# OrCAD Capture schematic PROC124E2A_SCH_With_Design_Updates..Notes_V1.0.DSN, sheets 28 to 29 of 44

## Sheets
28 27. XDS110 DEBUGGER: size C; title: XDS110 DEBUGGER
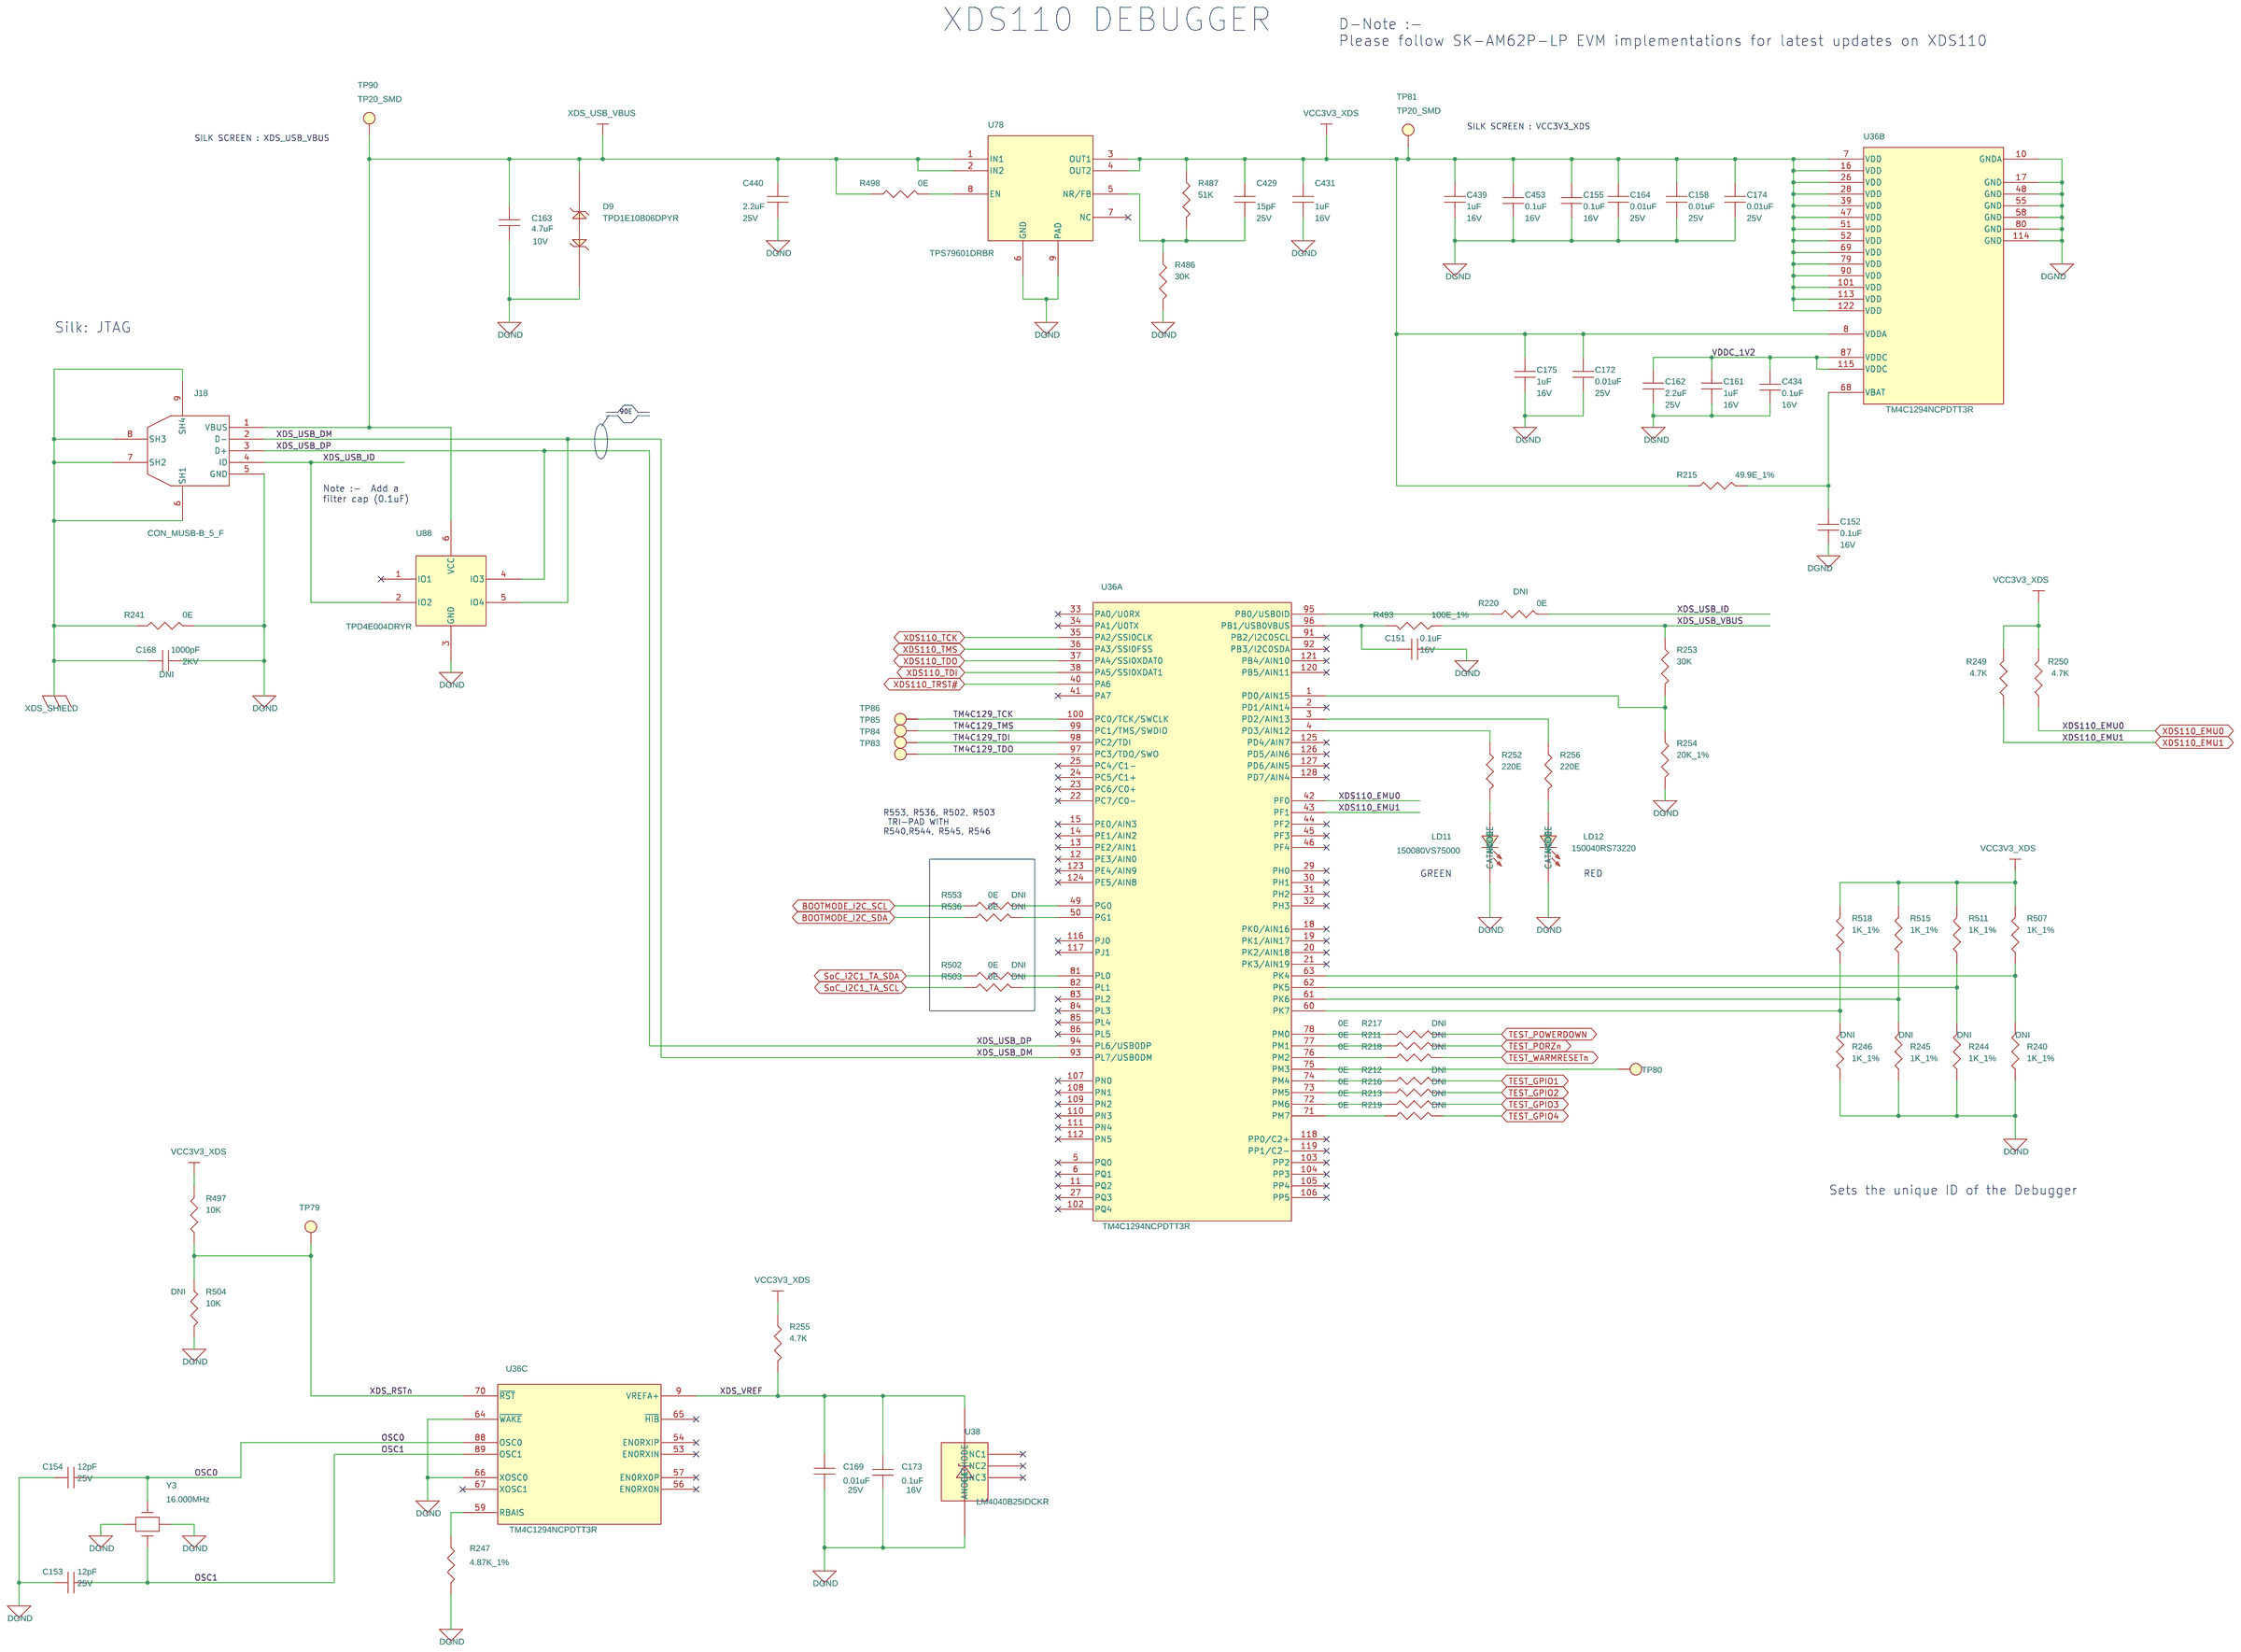
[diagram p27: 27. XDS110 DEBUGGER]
29 28. JTAG BUFFER: size C; title: JTAG BUFFER
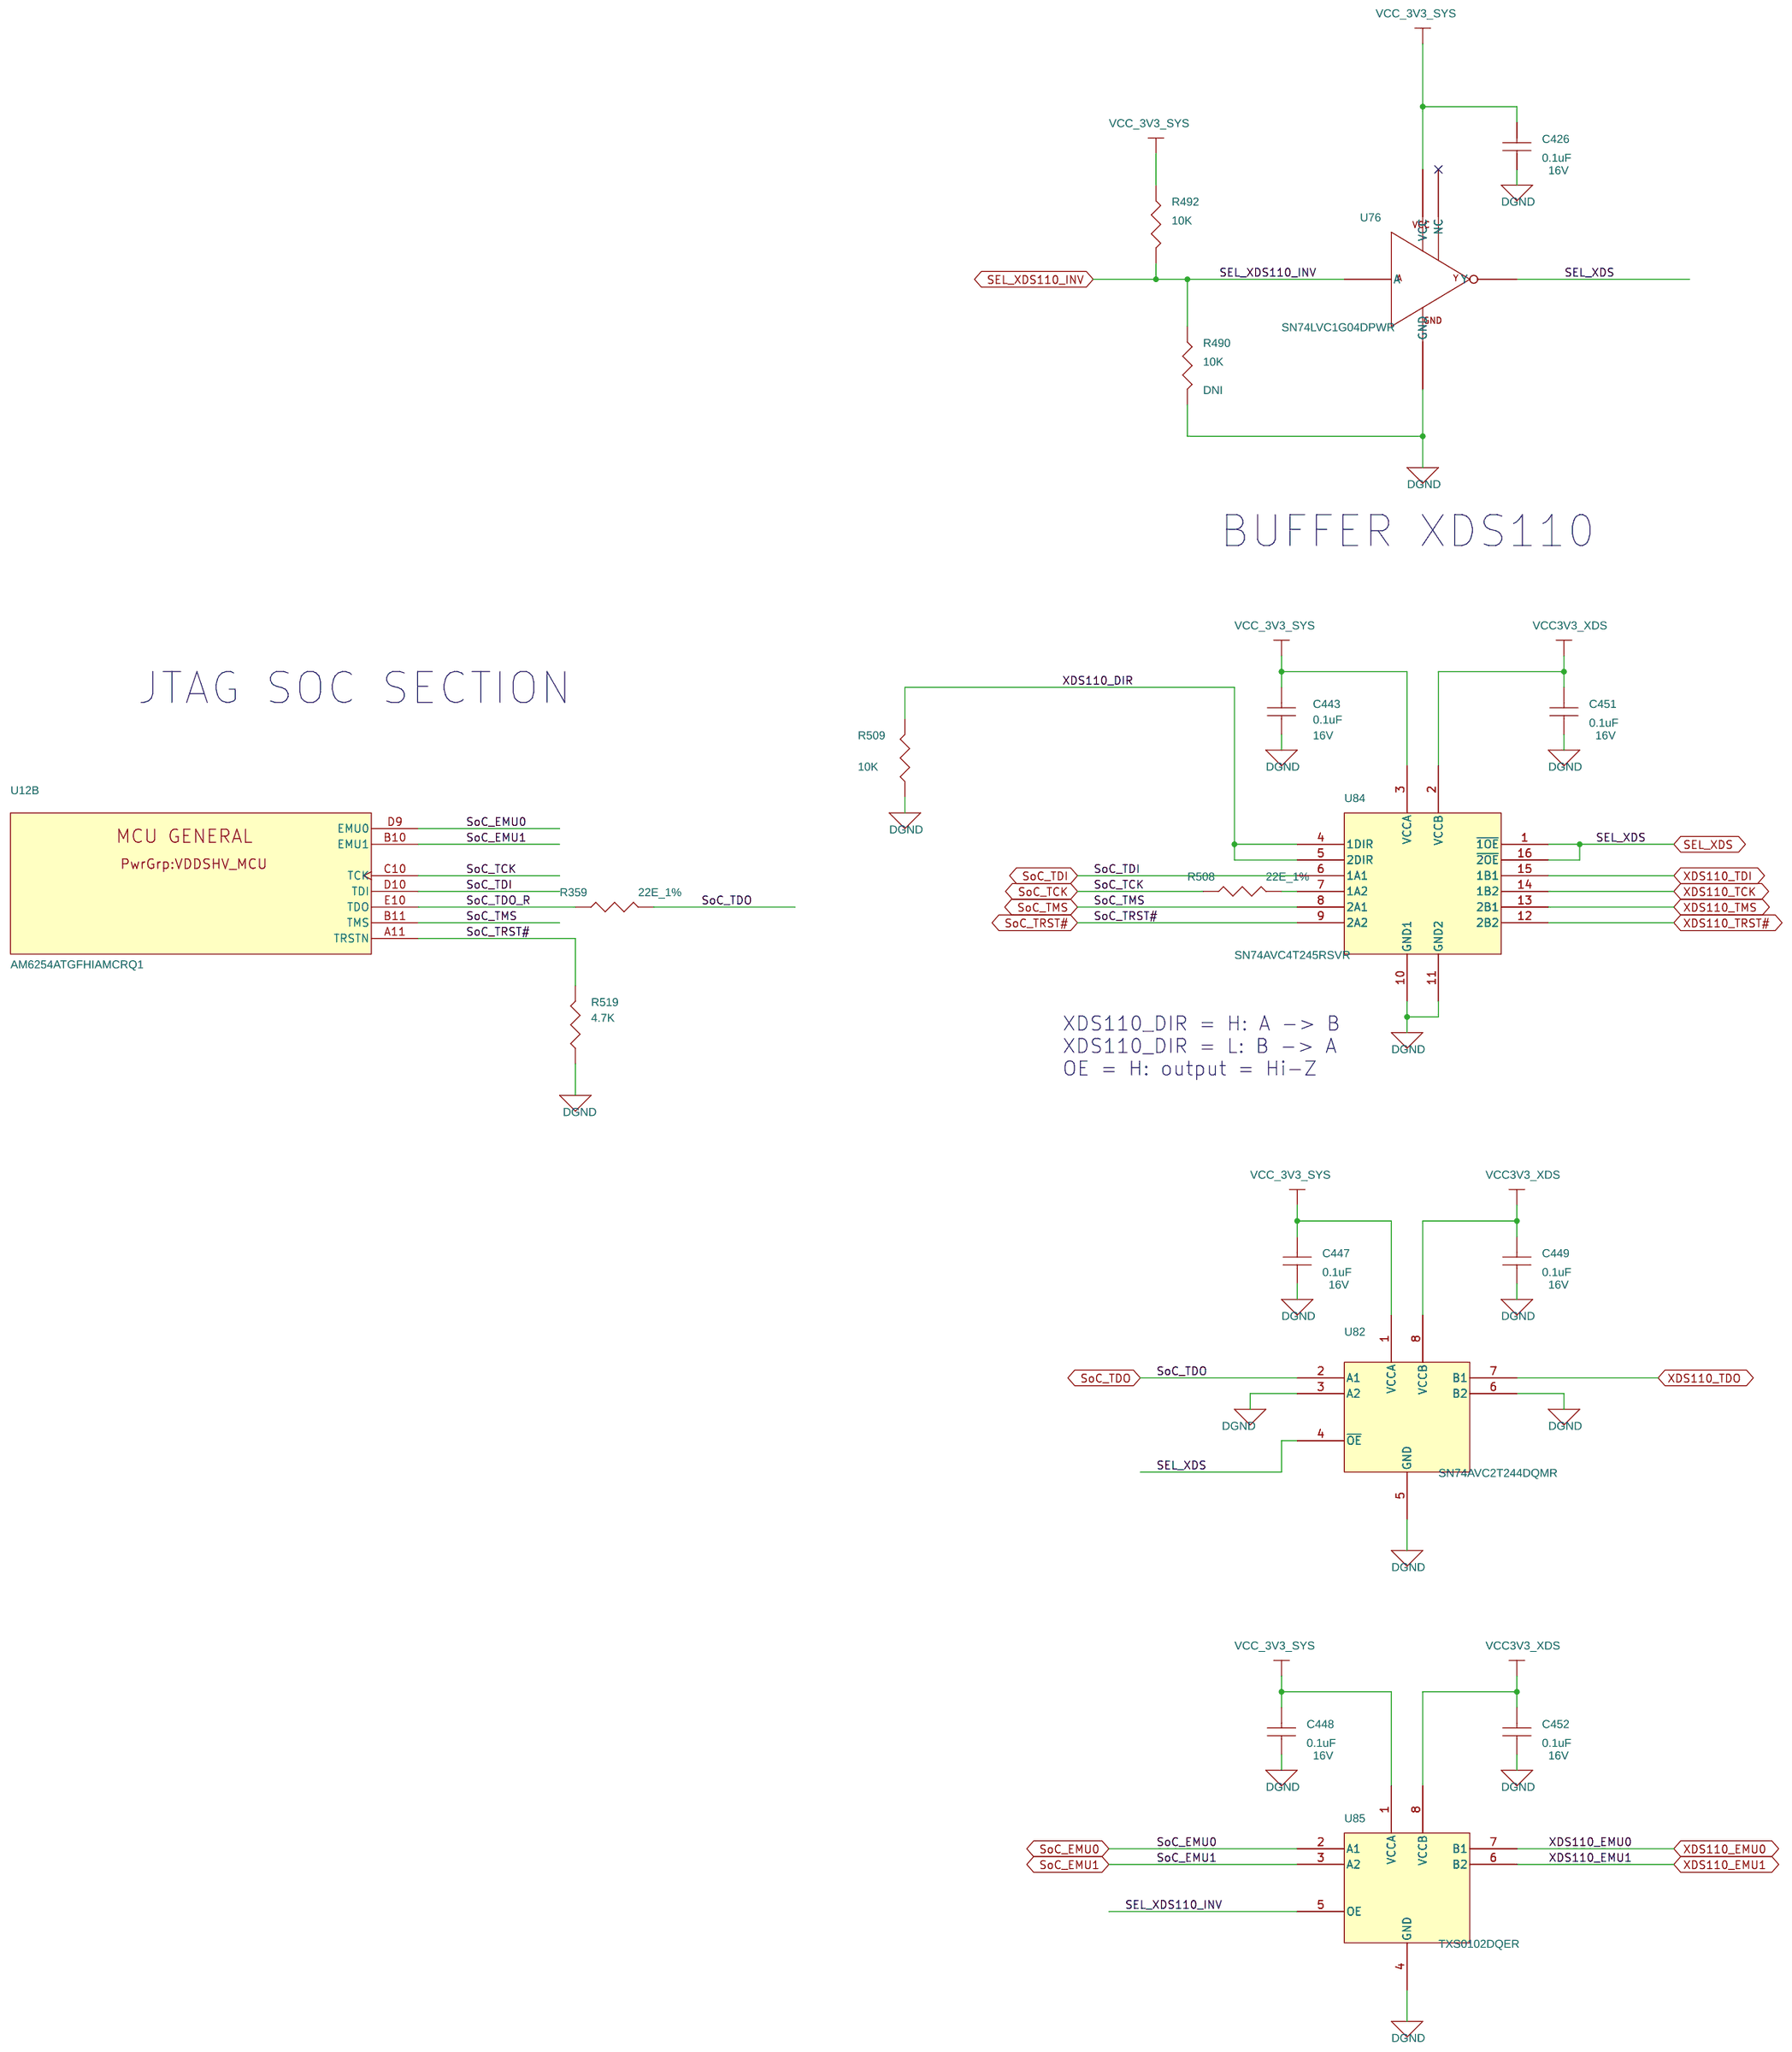
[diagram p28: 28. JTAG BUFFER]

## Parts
sheet 15. SOC POWER CAPS
U12  AM6254ATGFHIAMCRQ1  [FCBGA441_31-49_680X680_2-6]  (sections A,B,C,D,E,F,G,H,I,J,K,L,M,N,O,P,Q,R)
sheet 27. XDS110 DEBUGGER
C151  0.1uF  [CAP0201_0-5]
C152  0.1uF  [CAP0201_0-5]
C153  12pF  [CAP0201_0-5]
C154  12pF  [CAP0201_0-5]
C155  0.1uF  [CAP0201_0-5]
C158  0.01uF  [CAP0201_0-5]
C161  1uF  [CAP0201_0-5]
C162  2.2uF  [CAP0402_0-75]
C163  4.7uF  [CAP0402_0-75]
C164  0.01uF  [CAP0201_0-5]
C168  1000pF  [CAP1206_1-75]
C169  0.01uF  [CAP0201_0-5]
C172  0.01uF  [CAP0201_0-5]
C173  0.1uF  [CAP0201_0-5]
C174  0.01uF  [CAP0201_0-5]
C175  1uF  [CAP0201_0-5]
C429  15pF  [CAP0201_0-5]
C431  1uF  [CAP0201_0-5]
C434  0.1uF  [CAP0201_0-5]
C439  1uF  [CAP0201_0-5]
C440  2.2uF  [CAP0402_0-75]
C453  0.1uF  [CAP0201_0-5]
D9  TPD1E10B06DPYR  [DIO_DFN0402_0-5]
J18  CON_MUSB-B_5_F  [CON_MUSBB5_629105150521_S_R_S_2-7]
LD11  150080VS75000  [LED_150080VS75000_80X50_SMD_0-8]
LD12  150040RS73220  [LED_150040GS73220_40X20_SMD_0-4]
R211  0E  [RES0201_0-5]
R212  0E  [RES0201_0-5]
R213  0E  [RES0201_0-5]
R215  49.9E_1%  [RES0402_0-5]
R216  0E  [RES0201_0-5]
R217  0E  [RES0201_0-5]
R218  0E  [RES0201_0-5]
R219  0E  [RES0201_0-5]
R220  0E  [RES0201_0-5]
R240  1K_1%  [RES0402_0-5]
R241  0E  [RES0603_0-75]
R244  1K_1%  [RES0402_0-5]
R245  1K_1%  [RES0402_0-5]
R246  1K_1%  [RES0402_0-5]
R247  4.87K_1%  [RES0402_0-5]
R249  4.7K  [RES0201_0-5]
R250  4.7K  [RES0201_0-5]
R252  220E  [RES0402_0-5]
R253  30K  [RES0402_0-5]
R254  20K_1%  [RES0402_0-5]
R255  4.7K  [RES0201_0-5]
R256  220E  [RES0402_0-5]
R486  30K  [RES0402_0-5]
R487  51K  [RES0402_0-5]
R493  100E_1%  [RES0402_0-5]
R497  10K  [RES0201_0-5]
R498  0E  [RES0201_0-5]
R502  0E  [RES0201_0-5]
R503  0E  [RES0201_0-5]
R504  10K  [RES0201_0-5]
R507  1K_1%  [RES0402_0-5]
R511  1K_1%  [RES0402_0-5]
R515  1K_1%  [RES0402_0-5]
R518  1K_1%  [RES0402_0-5]
R536  0E  [RES0201_0-5]
R553  0E  [RES0201_0-5]
TP79  TP20_SMD  [TP20_SMD]
TP80  TP20_SMD  [TP20_SMD]
TP81  TP20_SMD  [TP20_SMD]
TP83  TP20_SMD  [TP20_SMD]
TP84  TP20_SMD  [TP20_SMD]
TP85  TP20_SMD  [TP20_SMD]
TP86  TP20_SMD  [TP20_SMD]
TP90  TP20_SMD  [TP20_SMD]
U36  TM4C1294NCPDTT3R  [TQFP128_15-74_550X550_1-2]  (sections A,B,C)
U38  LM4040B25IDCKR  [SC70-5_1-1]
U78  TPS79601DRBR  [SON8_25-59_130X130_1]
U88  TPD4E004DRYR  [SON6_19-68_40X60_PB_0-6]
Y3  16.000MHz  [XTAL4_XRCGB-FM_80X60_SMD_0-7]
sheet 28. JTAG BUFFER
C426  0.1uF  [CAP0201_0-5]
C443  0.1uF  [CAP0201_0-5]
C447  0.1uF  [CAP0201_0-5]
C448  0.1uF  [CAP0201_0-5]
C449  0.1uF  [CAP0201_0-5]
C451  0.1uF  [CAP0201_0-5]
C452  0.1uF  [CAP0201_0-5]
R359  22E_1%  [RES0201_0-5]
R490  10K  [RES0201_0-5]
R492  10K  [RES0201_0-5]
R508  22E_1%  [RES0201_0-5]
R509  10K  [RES0201_0-5]
R519  4.7K  [RES0201_0-5]
U76  SN74LVC1G04DPWR  [X2SON5_TLV7021_30X30_0-4]
U82  SN74AVC2T244DQMR  [X2SON8_15-74_70X50]
U84  SN74AVC4T245RSVR  [UQFN16_TMUX1574_70X100_0-6]
U85  TXS0102DQER  [X2SON8_TXS0102_40X60_0-4]

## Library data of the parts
U12 = AM6254ATGFHIAMCRQ1_FCBGA441: IC AM62Q SoC MICROPROCESSOR FCBGA441; Chkd/date: PRADEEP/180324; Crtd /date: TAMILARASU/180324; Custom_Duty: 15%; Customs_HS_Code: 85423100; Distributor_name: NA; Distributor_part_number: NA; Footprint Path: Y:\MIS_DATABASE\Library\ALTIUM_TOOL\PCB_FOOTPRINTS\Altium_Footprint_Lib.PcbLib; Height: 2.57MM; Library Path: Y:\MIS_DATABASE\Library\ALTIUM_TOOL\SCHEMATICS_PARTS\MS_MICROPROCESSOR_Library.schlib; Mfr_name: TEXAS INSTRUMENTS; Mistral Part No: 141224030001-R; Package: FCBGA441; Part_type: ICS\DIGITAL\MICROPROCESSOR; Project: TI_AM62Q_BRD; RoHS: NA; Temperature: NA; Tolerance: NA; Voltage: NA; Wattage: NA; Weight: NA; Datasheet: Y:\MIS_DATABASE\DATASHEETS\ICS\DIGITAL\MICROCONTROLLER\AM62Q-SoC.PDF
C151 C152 C155 C173 C426 C434 C443 C447-C449 C451-C453 = CAP: CAP CERAMIC 0.1uF 16V 10% X5R 0201; Alt_Mfr_name: YAGEO AMERICA; Alt_Mfr_part_number: CC0402KRX5R8BB104; Chkd/date: MANIRAJA/230118; Crtd /date: MANIRAJA/230118; Custom_Duty: 15%; Customs_HS_Code: 85322990; Distributor_name: DIGIKEY; Distributor_part_number: 490-14305-1-ND; Footprint Path: Y:\MIS_DATABASE\Library\ALTIUM_TOOL\PCB_FOOTPRINTS\Altium_Footprint_Lib.PcbLib; Height: 0.33MM; Library Path: Y:\MIS_DATABASE\Library\ALTIUM_TOOL\SCHEMATICS_PARTS\MS_DISCRETE_Library.schlib; Mfr_name: MURATA; Mfr_part_number: GRM033R61C104KE14D; Mistral Part No: 120009030072-R; Package: 0201; Part_type: CAPACITORS\CERAMIC; Project: TI_MAXIE_CPB; RoHS: RoHS; Temperature: -55°C+85°C; Tolerance: 10%; Voltage: 16V; Wattage: NA; Weight: 0.33mg; Datasheet: Y:\MIS_DATABASE\DATASHEETS\CAPACITORS\GRM033R61C104KE14.PDF
C153 C154 = CAP: CAP CERAMIC 12pF 25V 5% C0G(NP0) 0201; Chkd/date: MANIRAJA/020620; Crtd /date: ALVY/300520; Custom_Duty: 15%; Customs_HS_Code: 85322990; Distributor_name: DIGIKEY; Distributor_part_number: 490-3144-1-ND; Footprint Path: Y:\MIS_DATABASE\Library\ALTIUM_TOOL\PCB_FOOTPRINTS\Altium_Footprint_Lib.PcbLib; Height: 0.33MM; Library Path: Y:\MIS_DATABASE\Library\ALTIUM_TOOL\SCHEMATICS_PARTS\MS_DISCRETE_Library.schlib; Mfr_name: MURATA; Mfr_part_number: GRM0335C1E120JA01D; Mistral Part No: 120009030213-R; Package: 0201; Part_type: CAPACITORS\CERAMIC; Project: QCS610_NANOSOM; RoHS: RoHS; Temperature: -55°C+125°C; Tolerance: 5%; Voltage: 25V; Wattage: NA; Weight: 0.33mg; Datasheet: Y:\MIS_DATABASE\DATASHEETS\CAPACITORS\GRM0335C1E120JA01.PDF
C158 C164 C169 C172 C174 = CAP: CAP CERAMIC 0.01uF 25V 10% X5R 0201; Chkd/date: MANIRAJA/230118; Crtd /date: MANIRAJA/230118; Custom_Duty: 15%; Customs_HS_Code: 85322990; Distributor_name: DIGIKEY; Distributor_part_number: GRM033R61E103KA12J-ND; Footprint Path: Y:\MIS_DATABASE\Library\ALTIUM_TOOL\PCB_FOOTPRINTS\Altium_Footprint_Lib.PcbLib; Height: 0.33MM; Library Path: Y:\MIS_DATABASE\Library\ALTIUM_TOOL\SCHEMATICS_PARTS\MS_DISCRETE_Library.schlib; Mfr_name: MURATA; Mfr_part_number: GRM033R61E103KA12J; Mistral Part No: 120018010007-R; Package: 0201; Part_type: CAPACITORS\CERAMIC; Project: TI_MAXIE_CPB; RoHS: RoHS; Temperature: -55°C+85°C; Tolerance: 10%; Voltage: 25V; Wattage: NA; Weight: 0.33mg; Datasheet: Y:\MIS_DATABASE\DATASHEETS\CAPACITORS\GRM033R61E103KA12.PDF
C161 C175 C431 C439 = CAP: CAP CERAMIC 1uF 16V 20% X5R 0201; Chkd/date: MANIRAJA/300520; Crtd /date: ALVY/260520; Custom_Duty: 15%; Customs_HS_Code: 85322990; Distributor_name: DIGIKEY; Distributor_part_number: 490-18654-1-ND; Footprint Path: Y:\MIS_DATABASE\Library\ALTIUM_TOOL\PCB_FOOTPRINTS\Altium_Footprint_Lib.PcbLib; Height: 0.39MM; Library Path: Y:\MIS_DATABASE\Library\ALTIUM_TOOL\SCHEMATICS_PARTS\MS_DISCRETE_Library.schlib; Mfr_name: MURATA; Mfr_part_number: GRM033R61C105ME15D; Mistral Part No: 120018090038-R; Package: 0201; Part_type: CAPACITORS\CERAMIC; Project: QCS610_NANOSOM; RoHS: RoHS; Temperature: -55°C+85°C; Tolerance: 20%; Voltage: 16V; Wattage: NA; Weight: 0.33mg; Datasheet: Y:\MIS_DATABASE\DATASHEETS\CAPACITORS\GRM033R61C105ME15.PDF
C162 C440 = CAP: CAP CERAMIC 2.2uF 25V 10% X5R 0402; Chkd/date: ALVY/010721; Crtd /date: MANIRAJA/010721; Custom_Duty: 15%; Customs_HS_Code: 85322990; Distributor_name: DIGIKEY; Distributor_part_number: 490-12703-1-ND; Footprint Path: Y:\MIS_DATABASE\Library\ALTIUM_TOOL\PCB_FOOTPRINTS\Altium_Footprint_Lib.PcbLib; Height: 0.70MM; Library Path: Y:\MIS_DATABASE\Library\ALTIUM_TOOL\SCHEMATICS_PARTS\MS_DISCRETE_Library.schlib; Mfr_name: MURATA; Mfr_part_number: GRM155R61E225KE11D; Mistral Part No: 120015120001-R; Package: 0402; Part_type: CAPACITORS\CERAMIC; Project: TI_AM263X_CC; RoHS: RoHS; Temperature: -55°C+85°C; Tolerance: 10%; Voltage: 25V; Wattage: NA; Weight: 1.5mg; Datasheet: Y:\MIS_DATABASE\DATASHEETS\CAPACITORS\GRM155R61E225KE11.PDF
C163 = CAP: CAP CERAMIC 4.7uF 10V 20% X5R 0402; Chkd/date: MANIRAJA/110718; Crtd /date: ALVY/110718; Custom_Duty: 15%; Customs_HS_Code: 85322990; Distributor_name: DIGIKEY; Distributor_part_number: 490-14306-1-ND; Footprint Path: Y:\MIS_DATABASE\Library\ALTIUM_TOOL\PCB_FOOTPRINTS\Altium_Footprint_Lib.PcbLib; Height: 0.65MM; Library Path: Y:\MIS_DATABASE\Library\ALTIUM_TOOL\SCHEMATICS_PARTS\MS_DISCRETE_Library.schlib; Mfr_name: MURATA; Mfr_part_number: GRM155R61A475MEAAD; Mistral Part No: 120012060002-R; Package: 0402; Part_type: CAPACITORS\CERAMIC; Project: TI_J7SVB_PCIE_ADD-ON-CARD; RoHS: RoHS; Temperature: -55°C+85°C; Tolerance: 20%; Voltage: 10V; Wattage: NA; Weight: 14mg; Datasheet: Y:\MIS_DATABASE\DATASHEETS\CAPACITORS\GRM155R61A475MEAAD.PDF
C168 = CAP: CAP CERAMIC 1000pF 2KV 10% X7R 1206; Assembly_Instruction: DNI; Chkd/date: SHREESHAIL/291106; Crtd /date: MAZHAR/281106; Custom_Duty: 15%; Customs_HS_Code: 85322990; Distributor_name: DIGIKEY; Distributor_part_number: 478-2956-1-ND; Footprint Path: Y:\MIS_DATABASE\Library\ALTIUM_TOOL\PCB_FOOTPRINTS\Altium_Footprint_Lib.PcbLib; Height: 1.52MM; Library Path: Y:\MIS_DATABASE\Library\ALTIUM_TOOL\SCHEMATICS_PARTS\MS_DISCRETE_Library.schlib; Mfr_name: AVX CORPORATION; Mfr_part_number: 1206GC102KAT1A; Mistral Part No: 120015080006-R; Package: 1206; Part_type: CAPACITORS\CERAMIC; Project: ADR1B; RoHS: RoHS; Temperature: -55°C+125°C; Tolerance: 10%; Voltage: 2KV; Wattage: NA; Weight: 16.2mg; Datasheet: Y:\MIS_DATABASE\DATASHEETS\CAPACITORS\AVX_HV-MLC.PDF
C429 = CAP: CAP CERAMIC 15pF 25V 2% HI-Q C0G(NP0) 0201; Chkd/date: VASANTHA/081216; Crtd /date: MANIRAJA/081216; Custom_Duty: 15%; Customs_HS_Code: 85322990; Distributor_name: DIGIKEY; Distributor_part_number: 490-10562-1-ND; Footprint Path: Y:\MIS_DATABASE\Library\ALTIUM_TOOL\PCB_FOOTPRINTS\Altium_Footprint_Lib.PcbLib; Height: 0.33MM; Library Path: Y:\MIS_DATABASE\Library\ALTIUM_TOOL\SCHEMATICS_PARTS\MS_DISCRETE_Library.schlib; Mfr_name: MURATA; Mfr_part_number: GJM0335C1E150GB01D; Mistral Part No: 120016120011-R; Package: 0201; Part_type: CAPACITORS\CERAMIC; Project: OCTBTS5200; RoHS: RoHS; Temperature: -55°C+125°C; Tolerance: 2%; Voltage: 25V; Wattage: NA; Weight: 0.33mg; Datasheet: Y:\MIS_DATABASE\DATASHEETS\CAPACITORS\MURATA-GXX-SER_NOV17.PDF
D9 = DIODE_SOD323: DIODE 1CH ESD PROTECTION X1SON2; Chkd/date: MANIRAJA/040420; Crtd /date: VASANTHA/181114; Custom_Duty: 15%; Customs_HS_Code: 85423100; Distributor_name: DIGIKEY; Distributor_part_number: 296-30406-1-ND; Footprint Path: Y:\MIS_DATABASE\Library\ALTIUM_TOOL\PCB_FOOTPRINTS\Altium_Footprint_Lib.PcbLib; Height: 0.45MM; Library Path: Y:\MIS_DATABASE\Library\ALTIUM_TOOL\SCHEMATICS_PARTS\MS_DISCRETE_Library.schlib; Mfr_name: TEXAS INSTRUMENTS; Mistral Part No: 130014110022-R; Package: X1SON2; Part_type: DIODE; Project: GALILEO_EVM; RoHS: RoHS; Temperature: -40°C+125°C; Tolerance: NA; Voltage: NA; Wattage: NA; Weight: 1mg; Datasheet: Y:\MIS_DATABASE\DATASHEETS\ICS\INTERFACE\TPD1E10B06-SER.PDF
J18 = CON_USB_MINI-B: CON MICRO USB TYPE B 5POS FEMALE RT SMD; Chkd/date: MANIRAJA/150519; Crtd /date: ALVY/150519; Custom_Duty: 24%; Customs_HS_Code: 85369090; Distributor_name: DIGIKEY; Distributor_part_number: 732-5960-1-ND; Footprint Path: Y:\MIS_DATABASE\Library\ALTIUM_TOOL\PCB_FOOTPRINTS\Altium_Footprint_Lib.PcbLib; Height: 2.66MM; Library Path: Y:\MIS_DATABASE\Library\ALTIUM_TOOL\SCHEMATICS_PARTS\MS_CONNECTOR_Library.schlib; Mfr_name: WURTH ELECTRONICS; Mfr_part_number: 629105150521; Mistral Part No: 150019050015-R; Package: SMD; Part_type: CONNECTOR\USB; Project: NEXTNAV_ALT-STATION_ATE_BRD; RoHS: RoHS; Temperature: -40°C+85°C; Tolerance: NA; Voltage: NA; Wattage: NA; Weight: 360mg; Datasheet: Y:\MIS_DATABASE\DATASHEETS\CONNECTORS\629105150521.PDF
LD11 = DIODE_LED: DIODE LED BRIGHT GREEN SMD; Chkd/date: MANIRAJA/180820; Crtd /date: ALVY/180820; Custom_Duty: 24%; Customs_HS_Code: 85439000; Distributor_name: DIGIKEY; Distributor_part_number: 732-4986-1-ND; Footprint Path: Y:\MIS_DATABASE\Library\ALTIUM_TOOL\PCB_FOOTPRINTS\Altium_Footprint_Lib.PcbLib; Height: 0.80MM; Library Path: Y:\MIS_DATABASE\Library\ALTIUM_TOOL\SCHEMATICS_PARTS\MS_OPTO_Library.schlib; Mfr_name: WURTH ELECTRONICS; Mistral Part No: 130020080012-R; Package: SMD; Part_type: OPTO\LED; Project: AM64x_EVM_BRD; RoHS: RoHS; Temperature: -40°C+85°C; Tolerance: NA; Voltage: NA; Wattage: NA; Weight: 10mg; Datasheet: Y:\MIS_DATABASE\DATASHEETS\DISCRETES\LEDS\150080VS75000.PDF
LD12 = DIODE_LED: DIODE LED RED SMD; Chkd/date: MANIRAJA/100920; Crtd /date: ALVY/100920; Custom_Duty: 24%; Customs_HS_Code: 85439000; Distributor_name: DIGIKEY; Distributor_part_number: 732-13422-1-ND; Footprint Path: Y:\MIS_DATABASE\Library\ALTIUM_TOOL\PCB_FOOTPRINTS\Altium_Footprint_Lib.PcbLib; Height: 0.35MM; Library Path: Y:\MIS_DATABASE\Library\ALTIUM_TOOL\SCHEMATICS_PARTS\MS_OPTO_Library.schlib; Mfr_name: WURTH ELECTRONICS; Mistral Part No: 130020090020-R; Package: SMD; Part_type: OPTO\LED; Project: AM64X_SKEVM; RoHS: RoHS; Temperature: -40°C+85°C; Tolerance: NA; Voltage: NA; Wattage: NA; Weight: 29.3mg; Datasheet: Y:\MIS_DATABASE\DATASHEETS\DISCRETES\LEDS\150040RS73220.PDF
R211-R213 R216-R220 R502 R503 R536 R553 = RESISTOR: RES 0E 1/20W 5% 0201; Assembly_Instruction: DNI; Chkd/date: NAVEED/301214; Crtd /date: MUDDU/120710; Custom_Duty: 15%; Customs_HS_Code: 85332119; Distributor_name: DIGIKEY; Distributor_part_number: 311-0.0NCT-ND; Footprint Path: Y:\MIS_DATABASE\Library\ALTIUM_TOOL\PCB_FOOTPRINTS\Altium_Footprint_Lib.PcbLib; Height: 0.26MM; Library Path: Y:\MIS_DATABASE\Library\ALTIUM_TOOL\SCHEMATICS_PARTS\MS_DISCRETE_Library.schlib; Mfr_name: YAGEO AMERICA; Mfr_part_number: RC0201JR-070RL; Mistral Part No: 110010070067-R; Package: 0201; Part_type: RESISTORS\FIXED; Project: PB_BUGBASE; RoHS: RoHS; Temperature: -55°C+125°C; Tolerance: 5%; Voltage: NA; Wattage: 1/20W; Weight: 0.17mg; Datasheet: Y:\MIS_DATABASE\DATASHEETS\RESISTORS\RCXXXXL-SER_MAR18.PDF
R215 = RESISTOR: RES 49.9E 1/16W 1% 0402; Chkd/date: MANIRAJA/210519; Crtd /date: MANIRAJA/210519; Custom_Duty: 15%; Customs_HS_Code: 85332119; Distributor_name: DIGIKEY; Distributor_part_number: 541-3967-1-ND; Footprint Path: Y:\MIS_DATABASE\Library\ALTIUM_TOOL\PCB_FOOTPRINTS\Altium_Footprint_Lib.PcbLib; Height: 0.35MM; Library Path: Y:\MIS_DATABASE\Library\ALTIUM_TOOL\SCHEMATICS_PARTS\MS_DISCRETE_Library.schlib; Mfr_name: VISHAY; Mfr_part_number: CRCW040249R9FKEDC; Mistral Part No: 110009030846-R; Package: 0402; Part_type: RESISTORS\FIXED; Project: RFSU_RFTJ_CARD; RoHS: RoHS; Temperature: -55°C+155°C; Tolerance: 1%; Voltage: NA; Wattage: 1/16W; Weight: 0.65mg; Datasheet: Y:\MIS_DATABASE\DATASHEETS\RESISTORS\CRCW_C-SER.PDF
R240 R244-R246 = RESISTOR: RES 1K 1/10W 1% 0402; Assembly_Instruction: DNI; Chkd/date: VASANTHA/281216; Crtd /date: MAZHAR/150506; Custom_Duty: 15%; Customs_HS_Code: 85332119; Distributor_name: DIGIKEY; Distributor_part_number: P1.00KLCT-ND; Footprint Path: Y:\MIS_DATABASE\Library\ALTIUM_TOOL\PCB_FOOTPRINTS\Altium_Footprint_Lib.PcbLib; Height: 0.40MM; Library Path: Y:\MIS_DATABASE\Library\ALTIUM_TOOL\SCHEMATICS_PARTS\MS_DISCRETE_Library.schlib; Mfr_name: PANASONIC-ECG; Mfr_part_number: ERJ-2RKF1001X; Mistral Part No: 110009030411-R; Package: 0402; Part_type: RESISTORS\FIXED; Project: VOCERA; RoHS: RoHS; Temperature: -55°C+155°C; Tolerance: 1%; Voltage: NA; Wattage: 1/10W; Weight: 0.8mg; Datasheet: Y:\MIS_DATABASE\DATASHEETS\RESISTORS\PAN-ERJSER_NOV17.PDF
R241 = RESISTOR: RES 0E 1/10W 5% 0603; Chkd/date: MANIRAJA/051217; Crtd /date: BAVISH/180211; Custom_Duty: 15%; Customs_HS_Code: 85332119; Distributor_name: DIGIKEY; Distributor_part_number: 311-0.0GRCT-ND; Footprint Path: Y:\MIS_DATABASE\Library\ALTIUM_TOOL\PCB_FOOTPRINTS\Altium_Footprint_Lib.PcbLib; Height: 0.55MM; Library Path: Y:\MIS_DATABASE\Library\ALTIUM_TOOL\SCHEMATICS_PARTS\MS_DISCRETE_Library.schlib; Mfr_name: YAGEO AMERICA; Mfr_part_number: RC0603JR-070RL; Mistral Part No: 110011020013-R; Package: 0603; Part_type: RESISTORS\FIXED; Project: KENNEL; RoHS: RoHS; Temperature: -55°C+155°C; Tolerance: 5%; Voltage: NA; Wattage: 1/10W; Weight: 2mg; Datasheet: Y:\MIS_DATABASE\DATASHEETS\RESISTORS\RCXXXXL-SER_MAR18.PDF
R247 = RESISTOR: RES 4.87K 1/10W 1% 0402; Chkd/date: MAZHAR/150709; Crtd /date: USMAN/150109; Custom_Duty: 15%; Customs_HS_Code: 85332119; Distributor_name: DIGIKEY; Distributor_part_number: P4.87KLCT-ND; Footprint Path: Y:\MIS_DATABASE\Library\ALTIUM_TOOL\PCB_FOOTPRINTS\Altium_Footprint_Lib.PcbLib; Height: 0.40MM; Library Path: Y:\MIS_DATABASE\Library\ALTIUM_TOOL\SCHEMATICS_PARTS\MS_DISCRETE_Library.schlib; Mfr_name: PANASONIC-ECG; Mfr_part_number: ERJ-2RKF4871X; Mistral Part No: 110009030803-R; Package: 0402; Part_type: RESISTORS\FIXED; Project: BSN-II; RoHS: RoHS; Temperature: -55°C+155°C; Tolerance: 1%; Voltage: NA; Wattage: 1/10W; Weight: 0.8mg; Datasheet: Y:\MIS_DATABASE\DATASHEETS\RESISTORS\PAN-ERJSER_NOV17.PDF
R249 R250 R255 R519 = RESISTOR: RES 4.7K 1/20W 5% 0201; Chkd/date: MANIRAJA/200921; Crtd /date: ALVY/200921; Custom_Duty: 15%; Customs_HS_Code: 85332119; Distributor_name: DIGIKEY; Distributor_part_number: 311-4.7KNCT-ND; Footprint Path: Y:\MIS_DATABASE\Library\ALTIUM_TOOL\PCB_FOOTPRINTS\Altium_Footprint_Lib.PcbLib; Height: 0.26MM; Library Path: Y:\MIS_DATABASE\Library\ALTIUM_TOOL\SCHEMATICS_PARTS\MS_DISCRETE_Library.schlib; Mfr_name: YAGEO AMERICA; Mfr_part_number: RC0201JR-074K7L; Mistral Part No: 110021090007-R; Package: 0201; Part_type: RESISTORS\FIXED; Project: TI_AM62x SKEVM_BRD; RoHS: RoHS; Temperature: -55°C+125°C; Tolerance: 5%; Voltage: NA; Wattage: 1/20W; Weight: 0.17mg; Datasheet: Y:\MIS_DATABASE\DATASHEETS\RESISTORS\RCXXXXL-SER_MAR18.PDF
R252 R256 = RESISTOR: RES 220E 1/10W 5% 0402; Chkd/date: VASANTHA/291216; Crtd /date: GEETHA/260406; Custom_Duty: 15%; Customs_HS_Code: 85332119; Distributor_name: DIGIKEY; Distributor_part_number: P220JCT-ND; Footprint Path: Y:\MIS_DATABASE\Library\ALTIUM_TOOL\PCB_FOOTPRINTS\Altium_Footprint_Lib.PcbLib; Height: 0.40MM; Library Path: Y:\MIS_DATABASE\Library\ALTIUM_TOOL\SCHEMATICS_PARTS\MS_DISCRETE_Library.schlib; Mfr_name: PANASONIC-ECG; Mfr_part_number: ERJ-2GEJ221X; Mistral Part No: 110009030506-R; Package: 0402; Part_type: RESISTORS\FIXED; Project: RED EYE; RoHS: RoHS; Temperature: -55°C+155°C; Tolerance: 5%; Voltage: NA; Wattage: 1/10W; Weight: 0.8mg; Datasheet: Y:\MIS_DATABASE\DATASHEETS\RESISTORS\PAN-ERJSER_NOV17.PDF
R253 R486 = RESISTOR: RES 30K 1/16W 5% 0402; Chkd/date: MANIRAJA/230817; Crtd /date: MANIRAJA/230817; Custom_Duty: 15%; Customs_HS_Code: 85332119; Distributor_name: DIGIKEY; Distributor_part_number: 541-30KJCT-ND; Footprint Path: Y:\MIS_DATABASE\Library\ALTIUM_TOOL\PCB_FOOTPRINTS\Altium_Footprint_Lib.PcbLib; Height: 0.40MM; Library Path: Y:\MIS_DATABASE\Library\ALTIUM_TOOL\SCHEMATICS_PARTS\MS_DISCRETE_Library.schlib; Mfr_name: VISHAY; Mfr_part_number: CRCW040230K0JNED; Mistral Part No: 110017080023-R; Package: 0402; Part_type: RESISTORS\FIXED; Project: TI_MAXIE_CPB; RoHS: RoHS; Temperature: -55°C+155°C; Tolerance: 5%; Voltage: NA; Wattage: 1/16W; Weight: 0.65mg; Datasheet: Y:\MIS_DATABASE\DATASHEETS\RESISTORS\CRCW0603.PDF
R254 = RESISTOR: RES 20K 1/16W 1% 0402; Chkd/date: MANIRAJA/021120; Crtd /date: MANIRAJA/021120; Custom_Duty: 15%; Customs_HS_Code: 85332119; Distributor_name: DIGIKEY; Distributor_part_number: 541-20.0KLCT-ND; Footprint Path: Y:\MIS_DATABASE\Library\ALTIUM_TOOL\PCB_FOOTPRINTS\Altium_Footprint_Lib.PcbLib; Height: 0.40MM; Library Path: Y:\MIS_DATABASE\Library\ALTIUM_TOOL\SCHEMATICS_PARTS\MS_DISCRETE_Library.schlib; Mfr_name: VISHAY; Mfr_part_number: CRCW040220K0FKED; Mistral Part No: 110009030486-R; Package: 0402; Part_type: RESISTORS\FIXED; Project: VAGG_SBC_BRD; RoHS: RoHS; Temperature: -55°C+155°C; Tolerance: 1%; Voltage: NA; Wattage: 1/16W; Weight: 0.65mg; Datasheet: Y:\MIS_DATABASE\DATASHEETS\RESISTORS\CRCW0603.PDF
R487 = RESISTOR: RES 51K 1/16W 5% 0402; Chkd/date: MANIRAJA/230817; Crtd /date: MANIRAJA/230817; Custom_Duty: 15%; Customs_HS_Code: 85332119; Distributor_name: DIGIKEY; Distributor_part_number: 541-51KJCT-ND; Footprint Path: Y:\MIS_DATABASE\Library\ALTIUM_TOOL\PCB_FOOTPRINTS\Altium_Footprint_Lib.PcbLib; Height: 0.40MM; Library Path: Y:\MIS_DATABASE\Library\ALTIUM_TOOL\SCHEMATICS_PARTS\MS_DISCRETE_Library.schlib; Mfr_name: VISHAY; Mfr_part_number: CRCW040251K0JNED; Mistral Part No: 110009030966-R; Package: 0402; Part_type: RESISTORS\FIXED; Project: TI_MAXIE_CPB; RoHS: RoHS; Temperature: -55°C+155°C; Tolerance: 5%; Voltage: NA; Wattage: 1/16W; Weight: 0.65mg; Datasheet: Y:\MIS_DATABASE\DATASHEETS\RESISTORS\CRCW0603.PDF
R493 = RESISTOR: RES 100E 1/16W 1% 0402; Chkd/date: MANIRAJA/060318; Crtd /date: NAVEED/220714; Custom_Duty: 15%; Customs_HS_Code: 85332119; Distributor_name: DIGIKEY; Distributor_part_number: 311-100LRCT-ND; Footprint Path: Y:\MIS_DATABASE\Library\ALTIUM_TOOL\PCB_FOOTPRINTS\Altium_Footprint_Lib.PcbLib; Height: 0.40MM; Library Path: Y:\MIS_DATABASE\Library\ALTIUM_TOOL\SCHEMATICS_PARTS\MS_DISCRETE_Library.schlib; Mfr_name: YAGEO AMERICA; Mfr_part_number: RC0402FR-07100RL; Mistral Part No: 110014070015-R; Package: 0402; Part_type: RESISTORS\FIXED; Project: DLRU; RoHS: RoHS; Temperature: -55°C+155°C; Tolerance: 1%; Voltage: NA; Wattage: 1/16W; Weight: 0.65mg; Datasheet: Y:\MIS_DATABASE\DATASHEETS\RESISTORS\RCXXXXL-SER_MAR18.PDF
R492 R497 R509 = RESISTOR: RES 10K 1/20W 5% 0201; Chkd/date: MANIRAJA/050517; Crtd /date: MANIRAJA/050517; Custom_Duty: 15%; Customs_HS_Code: 85332119; Distributor_name: DIGIKEY; Distributor_part_number: 311-10KNCT-ND; Footprint Path: Y:\MIS_DATABASE\Library\ALTIUM_TOOL\PCB_FOOTPRINTS\Altium_Footprint_Lib.PcbLib; Height: 0.26MM; Library Path: Y:\MIS_DATABASE\Library\ALTIUM_TOOL\SCHEMATICS_PARTS\MS_DISCRETE_Library.schlib; Mfr_name: YAGEO AMERICA; Mfr_part_number: RC0201JR-0710KL; Mistral Part No: 110010070051-R; Package: 0201; Part_type: RESISTORS\FIXED; Project: GOLDEN-I LITE; RoHS: RoHS; Temperature: -55°C+125°C; Tolerance: 5%; Voltage: NA; Wattage: 1/20W; Weight: 0.17mg; Datasheet: Y:\MIS_DATABASE\DATASHEETS\RESISTORS\RCXXXXL-SER_MAR18.PDF
R498 = RESISTOR: RES 0E 1/20W 5% 0201; Chkd/date: NAVEED/301214; Crtd /date: MUDDU/120710; Custom_Duty: 15%; Customs_HS_Code: 85332119; Distributor_name: DIGIKEY; Distributor_part_number: 311-0.0NCT-ND; Footprint Path: Y:\MIS_DATABASE\Library\ALTIUM_TOOL\PCB_FOOTPRINTS\Altium_Footprint_Lib.PcbLib; Height: 0.26MM; Library Path: Y:\MIS_DATABASE\Library\ALTIUM_TOOL\SCHEMATICS_PARTS\MS_DISCRETE_Library.schlib; Mfr_name: YAGEO AMERICA; Mfr_part_number: RC0201JR-070RL; Mistral Part No: 110010070067-R; Package: 0201; Part_type: RESISTORS\FIXED; Project: PB_BUGBASE; RoHS: RoHS; Temperature: -55°C+125°C; Tolerance: 5%; Voltage: NA; Wattage: 1/20W; Weight: 0.17mg; Datasheet: Y:\MIS_DATABASE\DATASHEETS\RESISTORS\RCXXXXL-SER_MAR18.PDF
R490 R504 = RESISTOR: RES 10K 1/20W 5% 0201; Assembly_Instruction: DNI; Chkd/date: MANIRAJA/050517; Crtd /date: MANIRAJA/050517; Custom_Duty: 15%; Customs_HS_Code: 85332119; Distributor_name: DIGIKEY; Distributor_part_number: 311-10KNCT-ND; Footprint Path: Y:\MIS_DATABASE\Library\ALTIUM_TOOL\PCB_FOOTPRINTS\Altium_Footprint_Lib.PcbLib; Height: 0.26MM; Library Path: Y:\MIS_DATABASE\Library\ALTIUM_TOOL\SCHEMATICS_PARTS\MS_DISCRETE_Library.schlib; Mfr_name: YAGEO AMERICA; Mfr_part_number: RC0201JR-0710KL; Mistral Part No: 110010070051-R; Package: 0201; Part_type: RESISTORS\FIXED; Project: GOLDEN-I LITE; RoHS: RoHS; Temperature: -55°C+125°C; Tolerance: 5%; Voltage: NA; Wattage: 1/20W; Weight: 0.17mg; Datasheet: Y:\MIS_DATABASE\DATASHEETS\RESISTORS\RCXXXXL-SER_MAR18.PDF
R507 R511 R515 R518 = RESISTOR: RES 1K 1/10W 1% 0402; Chkd/date: VASANTHA/281216; Crtd /date: MAZHAR/150506; Custom_Duty: 15%; Customs_HS_Code: 85332119; Distributor_name: DIGIKEY; Distributor_part_number: P1.00KLCT-ND; Footprint Path: Y:\MIS_DATABASE\Library\ALTIUM_TOOL\PCB_FOOTPRINTS\Altium_Footprint_Lib.PcbLib; Height: 0.40MM; Library Path: Y:\MIS_DATABASE\Library\ALTIUM_TOOL\SCHEMATICS_PARTS\MS_DISCRETE_Library.schlib; Mfr_name: PANASONIC-ECG; Mfr_part_number: ERJ-2RKF1001X; Mistral Part No: 110009030411-R; Package: 0402; Part_type: RESISTORS\FIXED; Project: VOCERA; RoHS: RoHS; Temperature: -55°C+155°C; Tolerance: 1%; Voltage: NA; Wattage: 1/10W; Weight: 0.8mg; Datasheet: Y:\MIS_DATABASE\DATASHEETS\RESISTORS\PAN-ERJSER_NOV17.PDF
TP79 TP80 TP83-TP86 = TESTPOINT: TESTPOINT CIR 20 SMD; Chkd/date: SHREESHAIL/171006; Crtd /date: MAZHAR/171006; Custom_Duty: NA; Customs_HS_Code: NA; Distributor_name: NA; Distributor_part_number: NA; Footprint Path: Y:\MIS_DATABASE\Library\ALTIUM_TOOL\PCB_FOOTPRINTS\Altium_Footprint_Lib.PcbLib; Height: NA; Library Path: Y:\MIS_DATABASE\Library\ALTIUM_TOOL\SCHEMATICS_PARTS\MS_DISCRETE_Library.schlib; MECHANICAL 3D STEP FILE: NA; Mfr_name: LOCAL; Mistral Part No: NA; Package: SMD; Project: BT MODULE_CSRBC04; RoHS: NA; Temperature: NA; Tolerance: NA; Voltage: NA; Wattage: NA; Weight: NA; Datasheet: NA
TP81 TP90 = TESTPOINT: TESTPOINT CIR 20 SMD; Chkd/date: SHREESHAIL/171006; Crtd /date: MAZHAR/171006; Custom_Duty: NA; Customs_HS_Code: NA; Distributor_name: NA; Distributor_part_number: NA; Footprint Path: Y:\MIS_DATABASE\Library\ALTIUM_TOOL\PCB_FOOTPRINTS\Altium_Footprint_Lib.PcbLib; Height: NA; Library Path: Y:\MIS_DATABASE\Library\ALTIUM_TOOL\SCHEMATICS_PARTS\MS_DISCRETE_Library.schlib; MECHANICAL 3D STEP FILE: NA; Manufacturer: LOCAL; Mfr_name: LOCAL; Mistral Part No: NA; Package: SMD; Project: BT MODULE_CSRBC04; RoHS: NA; Temperature: NA; Tolerance: NA; Voltage: NA; Wattage: NA; Weight: NA; Datasheet: NA
U36 = TM4C1294NCPDTT3R_TQFP128: IC 32-BIT MICROCONTROLLER WITH 1MB FLASH TQFP128; Chkd/date: MANIRAJA/220817; Crtd /date: MANIRAJA/220817; Custom_Duty: 15%; Customs_HS_Code: 85423100; Distributor_name: DIGIKEY; Distributor_part_number: TM4C1294NCPDTT3R-ND; Height: 1.20MM; Mfr_name: TEXAS INSTRUMENTS; Mistral Part No: 141217080002-R; Package: TQF9128; Part_type: ICS\DIGITAL\MICROCONTROLLER; Project: TI_MAXIE_CPB; RoHS: RoHS; Temperature: -40°C+105°C; Tolerance: NA; Voltage: NA; Wattage: NA; Weight: 503.5mg; Datasheet: Y:\MIS_DATABASE\DATASHEETS\ICS\DIGITAL\MICROCONTROLLER\TM4C1294NCPD.PDF
U38 = LM4040B25IDCKR_SC70-5: IC PRECISION MICROPOWER SHUNT VOLTAGE REFERENCE SC70-5; Chkd/date: MANIRAJA/230817; Crtd /date: MANIRAJA/230817; Custom_Duty: 15%; Customs_HS_Code: 85423100; Distributor_name: DIGIKEY; Distributor_part_number: 296-20873-1-ND; Height: 1.10MM; Mfr_name: TEXAS INSTRUMENTS; Mistral Part No: 142017080015-R; Package: SC70-5; Part_type: ICS\POWER\VOLTAGE REGULATOR; Project: TI_MAXIE_CPB; RoHS: RoHS; Temperature: -40°C+85°C; Tolerance: NA; Voltage: NA; Wattage: NA; Weight: 30mg; Datasheet: Y:\MIS_DATABASE\DATASHEETS\ICS\POWER\LM4040B25I.PDF
U78 = TPS79601DRBR_SON8: IC 1A HIGH PSRR RF ADJ LDO LINEAR REGULATOR SON8; Chkd/date: MANIRAJA/030518; Crtd /date: MAZHAR/280809; Custom_Duty: 15%; Customs_HS_Code: 85423100; Distributor_name: DIGIKEY; Distributor_part_number: 296-23107-1-ND; Footprint Path: Y:\MIS_DATABASE\Library\ALTIUM_TOOL\PCB_FOOTPRINTS\Altium_Footprint_Lib.PcbLib; Height: 1.00MM; Library Path: Y:\MIS_DATABASE\Library\ALTIUM_TOOL\SCHEMATICS_PARTS\MS_MISCPOWER_Library.schlib; Mfr_name: TEXAS INSTRUMENTS; Mistral Part No: 142009080012-R; Package: SON8; Part_type: ICS\POWER\VOLTAGE REGULATOR; Project: DIO_TXRX; RoHS: RoHS; Temperature: -40°C+125°C; Tolerance: NA; Voltage: NA; Wattage: NA; Weight: 24mg; Datasheet: Y:\MIS_DATABASE\DATASHEETS\MISC\REGULATORS\TPS796XX.PDF
U88 = TPD4E004_SON6: IC 4-CH ESD PROTECTION ARRAY FOR HIGH SPEED DATA INTERFACE SON6; Chkd/date: MANIRAJA/100320; Crtd /date: MUDDU/010310; Custom_Duty: 15%; Customs_HS_Code: 85423100; Distributor_name: DIGIKEY; Distributor_part_number: 296-23618-1-ND; Footprint Path: Y:\MIS_DATABASE\Library\ALTIUM_TOOL\PCB_FOOTPRINTS\Altium_Footprint_Lib.PcbLib; Height: 0.60MM; Library Path: Y:\MIS_DATABASE\Library\ALTIUM_TOOL\SCHEMATICS_PARTS\MS_MISCINTERFACE_Library.schlib; Mfr_name: TEXAS INSTRUMENTS; Mistral Part No: 141010020012-R; Package: SON6; Part_type: ICS\INTERFACE; Project: BUG_BASE-II; RoHS: RoHS; Temperature: -40°C+85°C; Tolerance: NA; Voltage: NA; Wattage: NA; Weight: 3.2mg; Datasheet: Y:\MIS_DATABASE\DATASHEETS\ICS\INTERFACE\TPD4E004-SER.PDF
Y3 = CRY4_13: CRY 16.000MHz 8pF SMD; Chkd/date: MANIRAJA/151020; Crtd /date: ALVY/151020; Custom_Duty: 24%; Customs_HS_Code: 85439000; Distributor_name: DIGIKEY; Distributor_part_number: 490-18283-1-ND; Footprint Path: Y:\MIS_DATABASE\Library\ALTIUM_TOOL\PCB_FOOTPRINTS\Altium_Footprint_Lib.PcbLib; Height: 0.70MM; Library Path: Y:\MIS_DATABASE\Library\ALTIUM_TOOL\SCHEMATICS_PARTS\MS_DISCRETE_Library.schlib; Mfr_name: MURATA; Mfr_part_number: XRCGB16M000FXN01R0; Mistral Part No: 130020100044-R; Package: SMD; Part_type: CRYSTAL; Project: AM64X_SKEVM; RoHS: RoHS; Temperature: -30°C+85°C; Tolerance: NA; Voltage: NA; Wattage: NA; Weight: 195.4mg; Datasheet: Y:\MIS_DATABASE\DATASHEETS\MISC\CRY_OSC\XRCGB16M000FXN01R0.PDF
R359 R508 = RESISTOR: RES 22E 1/20W 1% 0201; Chkd/date: PRAVEEN/080922; Crtd /date: TAMILARASU/080922; Custom_Duty: 15%; Customs_HS_Code: 85332119; Distributor_name: DIGIKEY; Distributor_part_number: P122843CT-ND; Footprint Path: Y:\MIS_DATABASE\Library\ALTIUM_TOOL\PCB_FOOTPRINTS\Altium_Footprint_Lib.PcbLib; Height: 0.26MM; Library Path: Y:\MIS_DATABASE\Library\ALTIUM_TOOL\SCHEMATICS_PARTS\MS_DISCRETE_Library.schlib; Mfr_name: PANASONIC-ECG; Mfr_part_number: ERJ-1GNF22R0C; Mistral Part No: 110022090007-R; Package: 0201; Part_type: RESISTORS\FIXED; Project: SK AM62Q LP EVM BRD; RoHS: RoHS; Temperature: -55°C+125°C; Tolerance: 1%; Voltage: NA; Wattage: 1/20W; Weight: 0.15mg; Datasheet: Y:\MIS_DATABASE\DATASHEETS\RESISTORS\PAN-ERJSER_NOV17.PDF
U76 = SN74LVC1G04DCKR_SC70-5: IC SINGLE INVERTER GATE X2SON5; Chkd/date: MANIRAJA/141020; Crtd /date: ALVY/131020; Custom_Duty: 15%; Customs_HS_Code: 85423100; Distributor_name: DIGIKEY; Distributor_part_number: 296-37758-1-ND; Footprint Path: Y:\MIS_DATABASE\Library\ALTIUM_TOOL\PCB_FOOTPRINTS\Altium_Footprint_Lib.PcbLib; Height: 0.40MM; Library Path: Y:\MIS_DATABASE\Library\ALTIUM_TOOL\SCHEMATICS_PARTS\MS_GATE_Library.schlib; Mfr_name: TEXAS INSTRUMENTS; Mistral Part No: 141020100010-R; Package: X2SON5; Part_type: ICS\DIGITAL\GATES; Project: AM64X_SKEVM; RoHS: RoHS; Temperature: -40°C+125°C; Tolerance: NA; Voltage: NA; Wattage: NA; Weight: 0.6mg; Datasheet: Y:\MIS_DATABASE\DATASHEETS\ICS\DIGITAL\GATES\SN74LVC1G04XX.PDF
U82 = SN74AVC2T244DQMR_X2SON8: IC 2-BIT UNDIRECTIONAL VOLTAGE-LEVEL TRANSLATOR X2SON8; Chkd/date: VASANTHA/060516; Crtd /date: VASANTHA/030316; Customs_HS_Code: 15%; Distributor_name: DIGIKEY; Distributor_part_number: 296-29674-1-ND; Height: 0.40MM; Mfr_name: TEXAS INSTRUMENTS; Mistral Part No: 141016030002-R; Package: X2SON8; Part_type: ICS\INTERFACE\LEVEL TRANSLATOR; Pb-Free: 85423100; Project: OCTASIC_3600; RoHS: RoHS; Temperature: -40°C+85°C; Tolerance: NA; Voltage: NA; Wattage: NA; Weight: NA; Datasheet: Y:\MIS_DATABASE\DATASHEETS\ICS\INTERFACE\SN74AVC2T244.PDF
U84 = SN74AVC4T245RSV_UQFN16: IC 2-BIT BUS TRANSCEIVER WITH CONFIGURABLE VOLTAGE TRANSLATION AND 3 STATE O/P UQFN16; Chkd/date: MANIRAJA/040520; Crtd /date: BAVISH/190411; Custom_Duty: 15%; Customs_HS_Code: 85423100; Distributor_name: DIGIKEY; Distributor_part_number: 296-24366-1-ND; Footprint Path: Y:\MIS_DATABASE\Library\ALTIUM_TOOL\PCB_FOOTPRINTS\Altium_Footprint_Lib.PcbLib; Height: 0.55MM; Library Path: Y:\MIS_DATABASE\Library\ALTIUM_TOOL\SCHEMATICS_PARTS\MS_BUSDRIVERTRANSCEIVER_Library.schlib; Mfr_name: TEXAS INSTRUMENTS; Mistral Part No: 141011040011-R; Package: UQFN16; Part_type: ICS\DIGITAL\BUSTRANSCEIVER; Project: HMC; RoHS: RoHS; Temperature: -40°C+85°C; Tolerance: NA; Voltage: NA; Wattage: NA; Weight: 41mg; Datasheet: Y:\MIS_DATABASE\DATASHEETS\ICS\DIGITAL\BUSTRANSCEIVER\SN74AVC4T245-SER.PDF
U85 = TXS0102DQX_SON8: IC 2-BIT BI-DIR VOLTAGE-LEVEL TRANSLATOR FOR OPEN-DRAIN AND PUSH-PULL X2SON8; Chkd/date: MANIRAJA/010719; Crtd /date: CHAITHANYA230512; Custom_Duty: 15%; Customs_HS_Code: 85423100; Distributor_name: DIGIKEY; Distributor_part_number: 296-28368-1-ND; Footprint Path: Y:\MIS_DATABASE\Library\ALTIUM_TOOL\PCB_FOOTPRINTS\Altium_Footprint_Lib.PcbLib; Height: 0.40MM; Library Path: Y:\MIS_DATABASE\Library\ALTIUM_TOOL\SCHEMATICS_PARTS\MS_MISCINTERFACE_Library.schlib; Mfr_name: TEXAS INSTRUMENTS; Mistral Part No: 141012050010-R; Package: X2SON8; Part_type: ICS\INTERFACE\LEVEL TRANSLATOR; Project: GEN_3-8_DB; RoHS: RoHS; Temperature: -40°C+85°C; Tolerance: NA; Voltage: NA; Wattage: NA; Weight: 1.2mg; Datasheet: Y:\MIS_DATABASE\DATASHEETS\ICS\INTERFACE\TXS0102-SER.PDF

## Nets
DGND: C151.1 C152.1 C153.1 C154.1 C155.1 C158.2 C161.2 C162.2 C163.2 C164.2 C168.1 C169.2 C172.2 C173.1 C174.2 C175.2 C426.1 C431.2 C434.1 C439.2 C440.2 C443.1 C447.1 C448.1 C449.1 C451.1 C452.1 C453.1 D9.1 J18.5(GND) LD11.1(CATHODE) LD12.1(CATHODE) R240.1 R241.1 R244.1 R245.1 R246.1 R247.2 R254.2 R486.2 R490.1 R504.2 R509.1 R519.2 U36.10(GNDA) U36.17(GND) U36.48(GND) U36.55(GND) U36.58(GND) U36.64(~{WAKE}) U36.66(XOSC0) U36.80(GND) U36.114(GND) U38.1(ANODE) U76.3(GND) U78.6(GND) U78.9(PAD) U82.3(A2) U82.5(GND) U82.6(B2) U84.10(GND1) U84.11(GND2) U85.4(GND) U88.3(GND) Y3.2 Y3.4 ; also on sheet 1 2 3 4 13 14 15 16 17 18 19 20 21 22 23 24 25 26 27 30 31 32 33 34 35 36 37 38 39 40 41 42 43
VCC3V3_XDS: C155.2 C158.1 C164.1 C172.1 C174.1 C175.1 C429.1 C431.1 C439.1 C449.2 C451.2 C452.2 C453.2 R215.2 R249.1 R250.1 R255.1 R487.1 R497.2 R507.2 R511.2 R515.2 R518.2 TP81.1(TP) U36.7(VDD) U36.8(VDDA) U36.16(VDD) U36.26(VDD) U36.28(VDD) U36.39(VDD) U36.47(VDD) U36.51(VDD) U36.52(VDD) U36.69(VDD) U36.79(VDD) U36.90(VDD) U36.101(VDD) U36.113(VDD) U36.122(VDD) U78.3(OUT1) U78.4(OUT2) U82.8(VCCB) U84.2(VCCB) U85.8(VCCB) ; also on sheet 26
VCC_3V3_SYS: C426.2 C443.2 C447.2 C448.2 R492.2 U76.5(VCC) U82.1(VCCA) U84.3(VCCA) U85.1(VCCA) ; also on sheet 1 4 15 16 19 20 21 23 24 26 27 30 31 32 33 34 36 37 38 39 40 41 42 43
VDDC_1V2: C161.1 C162.1 C434.2 U36.87(VDDC) U36.115(VDDC)
BOOTMODE_I2C_SCL: R553.1 ; also on sheet 26 27
BOOTMODE_I2C_SDA: R536.1 ; also on sheet 26 27
OSC0: C154.2 U36.88(OSC0) Y3.3
OSC1: C153.2 U36.89(OSC1) Y3.1
SEL_XDS: U76.4(Y) U82.4(~{OE}) U84.1(~{1OE}) U84.16(~{2OE}) ; also on sheet 30
SEL_XDS110_INV: R490.2 R492.1 U76.2(A) U85.5(OE) ; also on sheet 30
SoC_EMU0: U12.D9(EMU0) U85.2(A1) ; also on sheet 30
SoC_EMU1: U12.B10(EMU1) U85.3(A2) ; also on sheet 30
SoC_I2C1_TA_SCL: R503.1 ; also on sheet 26
SoC_I2C1_TA_SDA: R502.1 ; also on sheet 26
SoC_TCK: R508.1 U12.C10(TCK) ; also on sheet 30
SoC_TDI: U12.D10(TDI) U84.6(1A1) ; also on sheet 30
SoC_TDO: R359.1 U82.2(A1) ; also on sheet 30
SoC_TDO_R: R359.2 U12.E10(TDO)
SoC_TMS: U12.B11(TMS) U84.8(2A1) ; also on sheet 30
SoC_TRST#: R519.1 U12.A11(TRSTN) U84.9(2A2) ; also on sheet 30
TEST_GPIO1: R212.2 ; also on sheet 26 43
TEST_GPIO2: R216.2 ; also on sheet 26 39
TEST_GPIO3: R213.2 ; also on sheet 26 27
TEST_GPIO4: R219.2 ; also on sheet 26 27
TEST_PORZn: R211.2 ; also on sheet 26 42
TEST_POWERDOWN: R217.2 ; also on sheet 4 14 26
TEST_WARMRESETn: R218.2 ; also on sheet 26 43
TM4C129_TCK: TP86.1(TP) U36.100(PC0/TCK/SWCLK)
TM4C129_TDI: TP84.1(TP) U36.98(PC2/TDI)
TM4C129_TDO: TP83.1(TP) U36.97(PC3/TDO/SWO)
TM4C129_TMS: TP85.1(TP) U36.99(PC1/TMS/SWDIO)
XDS110_DIR: R509.2 U84.4(1DIR) U84.5(2DIR)
XDS110_EMU0: R250.2 U36.42(PF0) U85.7(B1)
XDS110_EMU1: R249.2 U36.43(PF1) U85.6(B2)
XDS110_TCK: U36.35(PA2/SSI0CLK) U84.14(1B2)
XDS110_TDI: U36.38(PA5/SSI0XDAT1) U84.15(1B1)
XDS110_TDO: U36.37(PA4/SSI0XDAT0) U82.7(B1)
XDS110_TMS: U36.36(PA3/SSI0FSS) U84.13(2B1)
XDS110_TRST#: U36.40(PA6) U84.12(2B2)
XDS_RSTn: R497.1 R504.1 TP79.1(TP) U36.70(~{RST})
XDS_SHIELD: C168.2 J18.6(SH1) J18.7(SH2) J18.8(SH3) J18.9(SH4) R241.2
XDS_USB_DM: J18.2(D-) U36.93(PL7/USB0DM) U88.5(IO4)
XDS_USB_DP: J18.3(D+) U36.94(PL6/USB0DP) U88.4(IO3)
XDS_USB_ID: J18.4(ID) R220.2 U88.2(IO2)
XDS_USB_VBUS: C163.1 C440.1 D9.2 J18.1(VBUS) R253.1 R493.1 R498.1 TP90.1(TP) U78.1(IN1) U78.2(IN2) U88.6(VCC)
XDS_VREF: C169.1 C173.2 R255.2 U36.9(VREFA+) U38.3(CATHODE)
N16997746: R247.1 U36.59(RBAIS)
N17030208: R508.2 U84.7(1A2)
N17479799: R498.2 U78.8(EN)
N17479805: C429.2 R486.1 R487.2 U78.5(NR/FB)
N17479881: C152.2 R215.1 U36.68(VBAT)
N17481587: LD11.2(ANODE) R252.2
N17481598: C151.2 R493.2 U36.96(PB1/USB0VBUS)
N17481613: R220.1 U36.95(PB0/USB0ID)
N17481619: R253.2 R254.1 U36.1(PD0/AIN15)
N17481621: R246.2 R518.1 U36.60(PK7)
N17481627: R256.1 U36.3(PD2/AIN13)
N17481631: LD12.2(ANODE) R256.2
N17481633: R240.2 R507.1 U36.63(PK4)
N17481635: R245.2 R515.1 U36.61(PK6)
N17481637: R252.1 U36.4(PD3/AIN12)
N17481641: R244.2 R511.1 U36.62(PK5)
N18374616: R553.2 U36.49(PG0)
N18374619: R536.2 U36.50(PG1)
N18374622: R502.2 U36.81(PL0)
N18374625: R503.2 U36.82(PL1)
N21834326: R217.1 U36.78(PM0)
N21834328: R211.1 U36.77(PM1)
N21834330: R218.1 U36.76(PM2)
N21834332: R212.1 U36.74(PM4)
N21834361: R216.1 U36.73(PM5)
N21834363: R213.1 U36.72(PM6)
N21834365: R219.1 U36.71(PM7)
N21834376: TP80.1(TP) U36.75(PM3)

Not connected (* = marked no-connect by the designer): U36 2(PD1/AIN14)* 5(PQ0)* 6(PQ1)* 11(PQ2)* 12(PE3/AIN0)* 13(PE2/AIN1)* 14(PE1/AIN2)* 15(PE0/AIN3)* 18(PK0/AIN16)* 19(PK1/AIN17)* 20(PK2/AIN18)* 21(PK3/AIN19)* 22(PC7/C0-)* 23(PC6/C0+)* 24(PC5/C1+)* 25(PC4/C1-)* 27(PQ3)* 29(PH0)* 30(PH1)* 31(PH2)* 32(PH3)* 33(PA0/U0RX)* 34(PA1/U0TX)* 41(PA7)* 44(PF2)* 45(PF3)* 46(PF4)* 53(EN0RXIN)* 54(EN0RXIP)* 56(EN0RX0N)* 57(EN0RX0P)* 65(~{HIB})* 67(XOSC1)* 83(PL2)* 84(PL3)* 85(PL4)* 86(PL5)* 91(PB2/I2C0SCL)* 92(PB3/I2C0SDA)* 102(PQ4)* 103(PP2)* 104(PP3)* 105(PP4)* 106(PP5)* 107(PN0)* 108(PN1)* 109(PN2)* 110(PN3)* 111(PN4)* 112(PN5)* 116(PJ0)* 117(PJ1)* 118(PP0/C2+)* 119(PP1/C2-)* 120(PB5/AIN11)* 121(PB4/AIN10)* 123(PE4/AIN9)* 124(PE5/AIN8)* 125(PD4/AIN7)* 126(PD5/AIN6)* 127(PD6/AIN5)* 128(PD7/AIN4)*; U38 2(NC1)* 4(NC2)* 5(NC3)*; U76 1(NC)*; U78 7(NC)*; U88 1(IO1)*

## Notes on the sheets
sheet 28
- XDS110 DEBUGGER
- D-Note :-
  Please follow SK-AM62P-LP EVM implementations for latest updates on XDS110
- SILK SCREEN : XDS_USB_VBUS
- SILK SCREEN : VCC3V3_XDS
- Silk: JTAG
- 90E
- Note :-  Add a
  filter cap (0.1uF)
- R553, R536, R502, R503
   TRI-PAD WITH
  R540,R544, R545, R546
- GREEN
- RED
- Sets the unique ID of the Debugger
sheet 29
- BUFFER XDS110
- JTAG SOC SECTION
- XDS110_DIR = H: A -> B
  XDS110_DIR = L: B -> A
  OE = H: output = Hi-Z
